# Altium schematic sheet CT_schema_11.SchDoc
size 297 x 239 mm
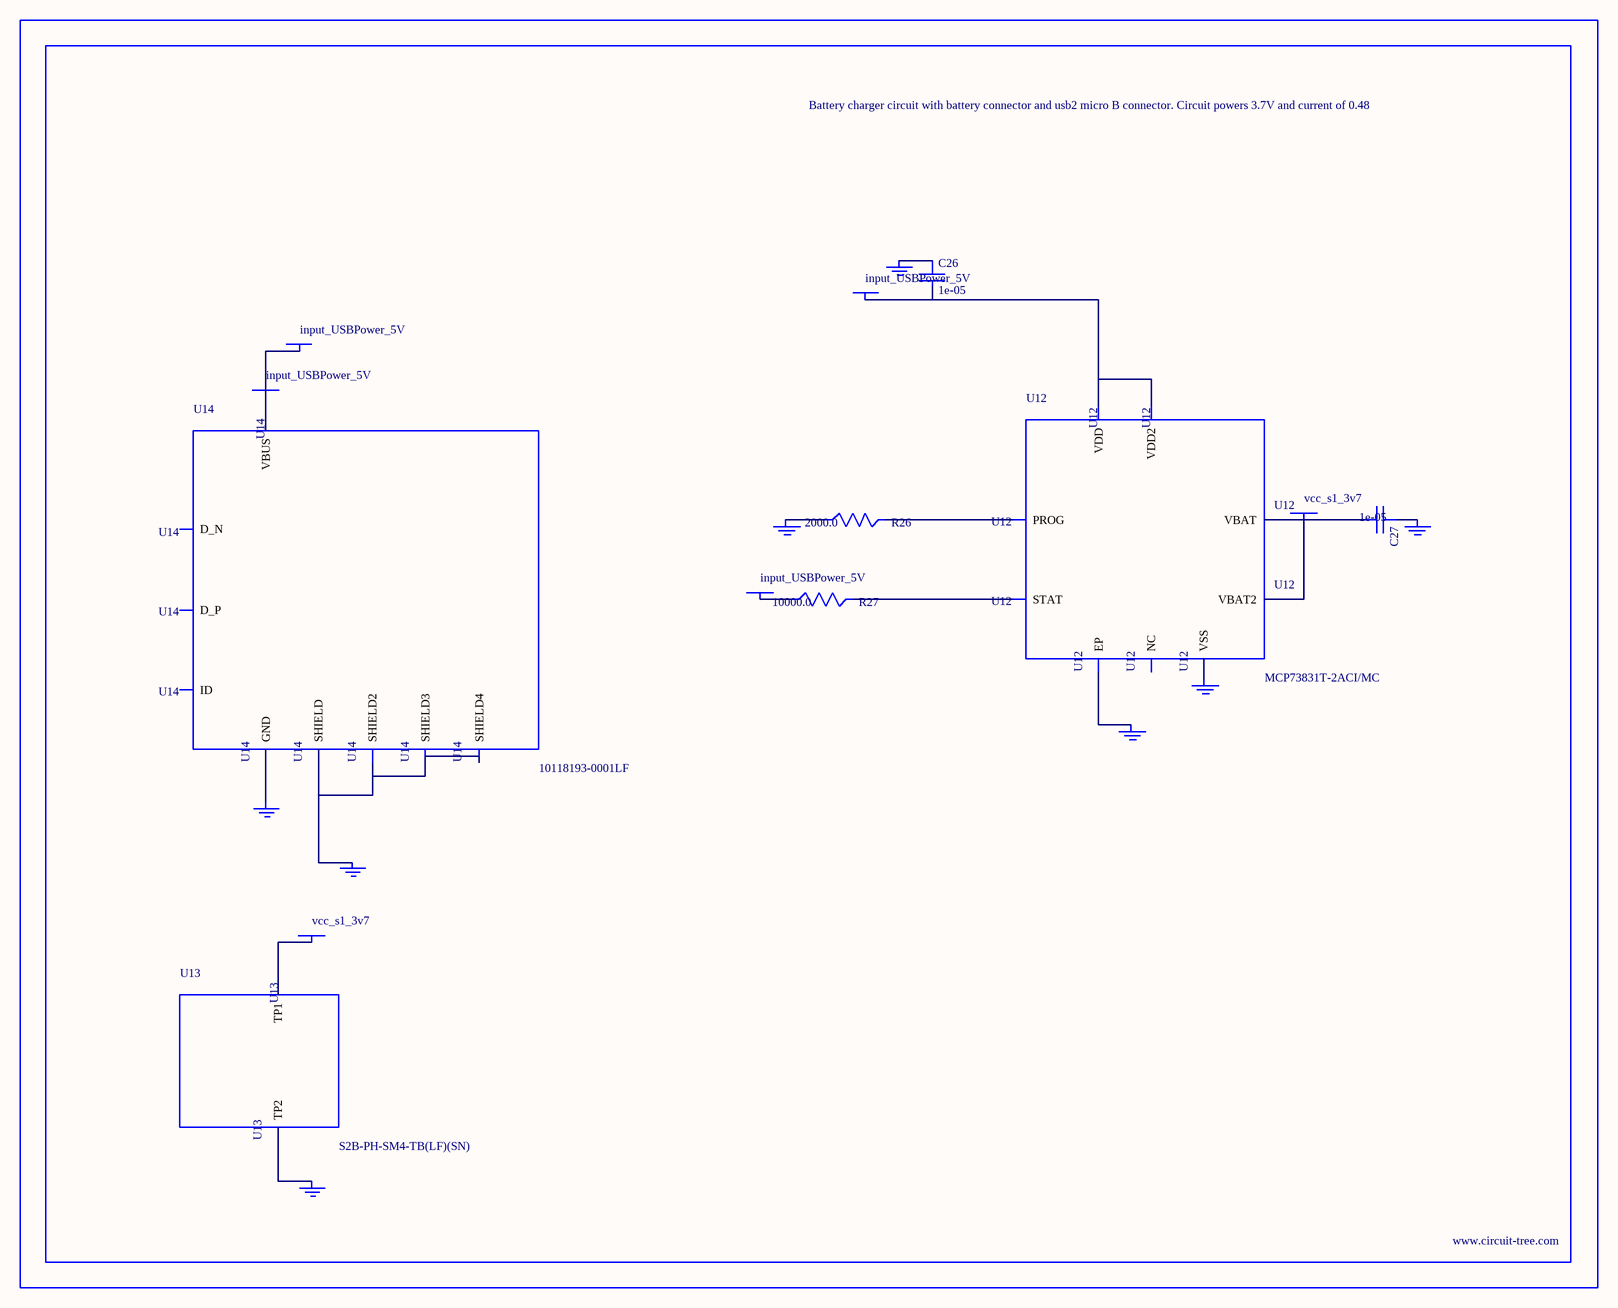
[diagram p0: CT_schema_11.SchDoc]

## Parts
BORDER10  (no value)
C26  1e-05  [C1206]
C27  1e-05  [C1206]
GND_INSTANCE_10_0  (no value)
GND_INSTANCE_10_1  (no value)
GND_INSTANCE_10_2  (no value)
GND_INSTANCE_10_3  (no value)
GND_INSTANCE_10_4  (no value)
GND_INSTANCE_10_5  (no value)
GND_INSTANCE_10_6  (no value)
GND_INSTANCE_10_7  (no value)
POWER_INSTANCE_10_0  input_USBPower_5V
POWER_INSTANCE_10_1  input_USBPower_5V
POWER_INSTANCE_10_2  vcc_s1_3v7
POWER_INSTANCE_10_3  vcc_s1_3v7
POWER_INSTANCE_10_4  input_USBPower_5V
POWER_INSTANCE_10_5  input_USBPower_5V
R26  2000.0  [R0603]
R27  10000.0  [R0603]
U12  MCP73831T-2ACI/MC  [DFN8_2X3MC]
U13  S2B-PH-SM4-TB(LF)(SN)  [JST-2-SMD]
U14  10118193-0001LF  [FCI_10118193-0001LF]

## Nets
NetC26_1: C26.1 GND_INSTANCE_10_0.0(GND)
NetC26_2: C26.2 POWER_INSTANCE_10_0.0(PWR) U12.1(VDD) U12.2(VDD2)
NetC27_1: C27.1 GND_INSTANCE_10_1.0(GND)
NetC27_2: C27.2 POWER_INSTANCE_10_2.0(PWR) U12.3(VBAT) U12.4(VBAT2)
NetGND_INSTANCE_10_2_0: GND_INSTANCE_10_2.0(GND) R26.1
NetGND_INSTANCE_10_3_0: GND_INSTANCE_10_3.0(GND) U12.9(EP)
NetGND_INSTANCE_10_4_0: GND_INSTANCE_10_4.0(GND) U12.6(VSS)
NetGND_INSTANCE_10_5_0: GND_INSTANCE_10_5.0(GND) U13.2(TP2)
NetGND_INSTANCE_10_6_0: GND_INSTANCE_10_6.0(GND) U14.6(SHIELD) U14.7(SHIELD2) U14.8(SHIELD3) U14.9(SHIELD4)
NetGND_INSTANCE_10_7_0: GND_INSTANCE_10_7.0(GND) U14.5(GND)
NetPOWER_INSTANCE_10_1_0: POWER_INSTANCE_10_1.0(PWR) R27.1
NetPOWER_INSTANCE_10_3_0: POWER_INSTANCE_10_3.0(PWR) U13.1(TP1)
NetPOWER_INSTANCE_10_4_0: POWER_INSTANCE_10_4.0(PWR) POWER_INSTANCE_10_5.0(PWR) U14.1(VBUS)
NetR26_2: R26.2 U12.8(PROG)
NetR27_2: R27.2 U12.5(STAT)

Not connected (* = marked no-connect by the designer): U12 7(NC); U14 2(D_N) 3(D_P) 4(ID)

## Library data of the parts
BORDER10 = BORDER_PAGE10
C26 C27 = C1206C106K3RACTU
GND_INSTANCE_10_0-GND_INSTANCE_10_7 = GND
POWER_INSTANCE_10_0-POWER_INSTANCE_10_5 = PWR
R26 = RC0603JR-072KL
R27 = RC0603JR-0710KL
